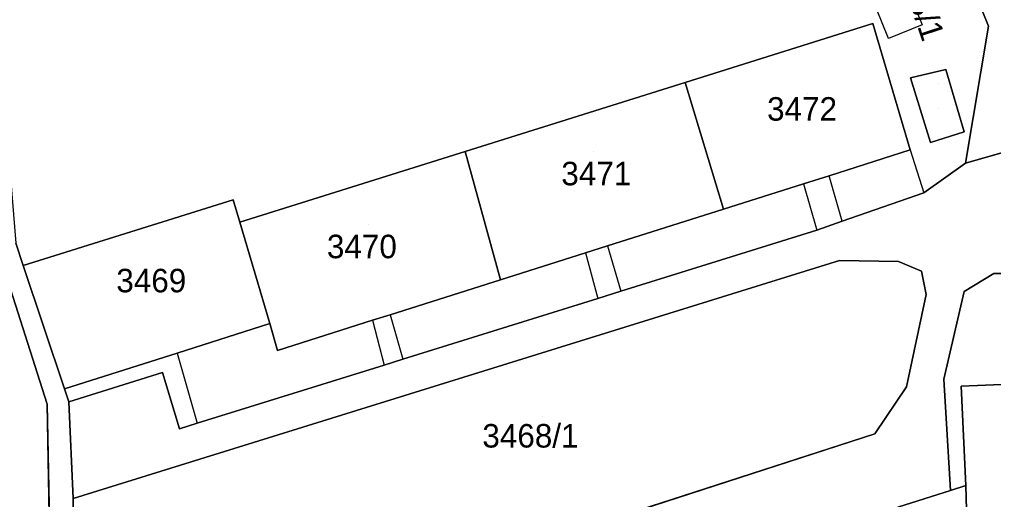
# Model space of a CAD drawing. Extents: x -264070 to -262271, y -1238894 to -1238141.
# Drawn here: x -262871.5 to -262788.6, y -1238496.4 to -1238455.5 of the extents above; entities that cross this region are included whole.
import ezdxf

# ---------------------------------------------------------------- set-up
doc = ezdxf.new("R2010")
doc.units = 0
for name, color, linetype in [('body_kn', 7, 'Continuous'), ('kladpar_druhypozemkov', 7, 'Continuous'), ('kladpar_hranice', 7, 'Continuous'), ('kladpar_parcelnecisla', 7, 'Continuous'), ('kladpar_plochy', 7, 'Continuous'), ('kladpar_sipky', 7, 'Continuous'), ('tarchy_linie', 7, 'Continuous'), ('zappar_hrandruhpozemk', 7, 'Continuous')]:
    doc.layers.add(name, color=color, linetype=linetype)

msp = doc.modelspace()

# ---------------------------------------------------------------- linework, layer by layer
at = {"layer": 'body_kn'}
for p, q in [((-262798.88, -1238455.89), (-262798.88, -1238455.89)), ((-262798.88, -1238455.89), (-262798.88, -1238455.89)), ((-262794.68, -1238456.01), (-262794.68, -1238456.01)), ((-262789.05, -1238456.12), (-262789.05, -1238456.12)), ((-262797.54, -1238457.17), (-262797.54, -1238457.17)), ((-262792.67, -1238459.81), (-262792.67, -1238459.81)), ((-262792.67, -1238459.81), (-262792.67, -1238459.81)), ((-262814.84, -1238460.9), (-262814.84, -1238460.9)), ((-262814.84, -1238460.9), (-262814.84, -1238460.9)), ((-262795.68, -1238460.51), (-262795.68, -1238460.51)), ((-262791.11, -1238465.11), (-262791.11, -1238465.11)), ((-262793.97, -1238466), (-262793.97, -1238466)), ((-262833.57, -1238466.77), (-262833.57, -1238466.77)), ((-262833.57, -1238466.77), (-262833.57, -1238466.77)), ((-262795.7, -1238466.64), (-262795.7, -1238466.64)), ((-262795.7, -1238466.64), (-262795.7, -1238466.64)), ((-262791, -1238467.76), (-262791, -1238467.76)), ((-262802.6, -1238468.83), (-262802.6, -1238468.83)), ((-262804.79, -1238469.52), (-262804.79, -1238469.52)), ((-262804.79, -1238469.52), (-262804.79, -1238469.52)), ((-262794.56, -1238470.28), (-262794.56, -1238470.28)), ((-262853.31, -1238470.87), (-262853.31, -1238470.87)), ((-262853.31, -1238470.87), (-262853.31, -1238470.87)), ((-262811.58, -1238471.67), (-262811.58, -1238471.67)), ((-262852.74, -1238472.78), (-262852.74, -1238472.78)), ((-262801.49, -1238472.7), (-262801.49, -1238472.7)), ((-262801.49, -1238472.7), (-262801.49, -1238472.7)), ((-262803.65, -1238473.46), (-262803.65, -1238473.46)), ((-262821.46, -1238474.8), (-262821.46, -1238474.8)), ((-262821.46, -1238474.8), (-262821.46, -1238474.8)), ((-262823.33, -1238475.39), (-262823.33, -1238475.39)), ((-262823.33, -1238475.39), (-262823.33, -1238475.39)), ((-262801.73, -1238476.05), (-262801.73, -1238476.05)), ((-262801.73, -1238476.05), (-262801.73, -1238476.05)), ((-262871.16, -1238476.48), (-262871.16, -1238476.48)), ((-262796.69, -1238476.13), (-262796.69, -1238476.13)), ((-262830.55, -1238477.68), (-262830.55, -1238477.68)), ((-262794.75, -1238476.95), (-262794.75, -1238476.95)), ((-262822.28, -1238479.26), (-262822.28, -1238479.26)), ((-262820.33, -1238478.65), (-262820.33, -1238478.65)), ((-262794.34, -1238478.93), (-262794.34, -1238478.93)), ((-262791.12, -1238478.68), (-262791.12, -1238478.68)), ((-262839.96, -1238480.66), (-262839.96, -1238480.66)), ((-262839.96, -1238480.66), (-262839.96, -1238480.66)), ((-262850.19, -1238481.41), (-262850.19, -1238481.41)), ((-262841.46, -1238481.13), (-262841.46, -1238481.13)), ((-262841.46, -1238481.13), (-262841.46, -1238481.13)), ((-262858.08, -1238483.92), (-262858.08, -1238483.92)), ((-262858.08, -1238483.92), (-262858.08, -1238483.92)), ((-262849.54, -1238483.69), (-262849.54, -1238483.69)), ((-262840.47, -1238484.93), (-262840.47, -1238484.93)), ((-262838.88, -1238484.43), (-262838.88, -1238484.43)), ((-262859.32, -1238485.56), (-262859.32, -1238485.56)), ((-262796.01, -1238486.8), (-262796.01, -1238486.8)), ((-262792.85, -1238486.14), (-262792.85, -1238486.14)), ((-262791.38, -1238486.73), (-262791.38, -1238486.73)), ((-262867.65, -1238486.97), (-262867.65, -1238486.97)), ((-262869.12, -1238488.27), (-262869.12, -1238488.27)), ((-262867.28, -1238488.07), (-262867.28, -1238488.07)), ((-262856.37, -1238489.88), (-262856.37, -1238489.88)), ((-262857.86, -1238490.35), (-262857.86, -1238490.35)), ((-262798.71, -1238490.79), (-262798.71, -1238490.79)), ((-262792.28, -1238495.59), (-262792.28, -1238495.59)), ((-262792.28, -1238495.59), (-262792.28, -1238495.59)), ((-262790.97, -1238495.17), (-262790.97, -1238495.17)), ((-262866.91, -1238496.29), (-262866.91, -1238496.29))]:
    msp.add_line(p, q, dxfattribs=at)
at = {"layer": 'kladpar_druhypozemkov'}
for p, q in [((-262804.43, -1238461.85), (-262804.43, -1238461.85)), ((-262793.31, -1238463.11), (-262793.31, -1238463.11)), ((-262822.63, -1238466.75), (-262822.63, -1238466.75)), ((-262841.83, -1238472.95), (-262841.83, -1238472.95)), ((-262859.63, -1238476.45), (-262859.63, -1238476.45)), ((-262827.03, -1238489.35), (-262827.03, -1238489.35))]:
    msp.add_line(p, q, dxfattribs=at)
at = {"layer": 'kladpar_hranice'}
for points in [[(-262813.03, -1238423.69), (-262816.48, -1238412.84), (-262832.44, -1238417.74), (-262850.86, -1238423.39), (-262870.49, -1238429.42), (-262871.1, -1238427.48), (-262888.61, -1238433.21), (-262885.22, -1238444.06), (-262877.38, -1238441.43), (-262874.97, -1238450.05), (-262873.29, -1238475.29), (-262869.12, -1238488.27), (-262868.55, -1238519.74), (-262897.95, -1238490.56), (-262896.25, -1238489.53), (-262912.76, -1238461.97), (-262925.07, -1238441.97), (-262929.57, -1238426.37), (-262924.66, -1238395.24), (-262923.4, -1238385.27), (-262921.26, -1238376.48), (-262918.98, -1238368.62), (-262909.71, -1238368.87)], [(-262786.55, -1238466.5), (-262791, -1238467.76), (-262789.05, -1238456.12), (-262800.89, -1238426.81), (-262801.71, -1238424.83), (-262809.3, -1238407.15)], [(-262839.65, -1238435.96), (-262838.66, -1238435.66), (-262837.63, -1238435.36), (-262821.25, -1238430.56), (-262819.19, -1238429.96), (-262811.78, -1238427.78), (-262801.71, -1238424.83), (-262800.89, -1238426.81), (-262841.06, -1238439.47), (-262873.85, -1238449.49), (-262871.8, -1238474.58), (-262871.16, -1238476.48), (-262867.65, -1238486.97), (-262867.28, -1238488.07), (-262866.91, -1238496.29), (-262866.54, -1238519.8)], [(-262800.89, -1238426.81), (-262789.05, -1238456.12), (-262791, -1238467.76), (-262794.56, -1238470.28), (-262801.49, -1238472.7), (-262803.65, -1238473.46), (-262820.33, -1238478.65), (-262822.28, -1238479.26), (-262838.88, -1238484.43), (-262840.47, -1238484.93), (-262856.37, -1238489.88), (-262857.86, -1238490.35), (-262859.32, -1238485.56), (-262867.28, -1238488.07), (-262867.65, -1238486.97), (-262858.08, -1238483.92), (-262850.19, -1238481.41), (-262849.54, -1238483.69), (-262841.46, -1238481.13), (-262839.96, -1238480.66), (-262830.55, -1238477.68), (-262823.33, -1238475.39), (-262821.46, -1238474.8), (-262811.58, -1238471.67), (-262804.79, -1238469.52), (-262802.6, -1238468.83), (-262795.7, -1238466.64), (-262798.88, -1238455.89), (-262814.84, -1238460.9), (-262833.57, -1238466.77), (-262852.74, -1238472.78), (-262853.31, -1238470.87), (-262871.16, -1238476.48), (-262871.8, -1238474.58)], [(-262868.55, -1238519.74), (-262869.12, -1238488.27), (-262873.29, -1238475.29), (-262874.97, -1238450.05), (-262877.38, -1238441.43), (-262875.45, -1238440.82), (-262873.87, -1238446.1), (-262858.47, -1238441.53), (-262856.5, -1238440.95), (-262839.65, -1238435.96)], [(-262798.88, -1238455.89), (-262795.7, -1238466.64), (-262802.6, -1238468.83), (-262804.79, -1238469.52), (-262811.58, -1238471.67), (-262814.84, -1238460.9), (-262798.88, -1238455.89)], [(-262795.68, -1238460.51), (-262793.97, -1238466), (-262791.11, -1238465.11), (-262792.67, -1238459.81), (-262795.68, -1238460.51)], [(-262792.67, -1238459.81), (-262791.11, -1238465.11), (-262793.97, -1238466), (-262795.68, -1238460.51), (-262792.67, -1238459.81)], [(-262814.84, -1238460.9), (-262811.58, -1238471.67), (-262821.46, -1238474.8), (-262823.33, -1238475.39), (-262830.55, -1238477.68), (-262833.57, -1238466.77), (-262814.84, -1238460.9)], [(-262822.66, -1238498.53), (-262798.71, -1238490.79), (-262796.01, -1238486.8), (-262794.34, -1238478.93), (-262794.75, -1238476.95), (-262796.69, -1238476.13), (-262801.73, -1238476.05), (-262866.91, -1238496.29), (-262867.28, -1238488.07), (-262859.32, -1238485.56), (-262857.86, -1238490.35), (-262856.37, -1238489.88), (-262840.47, -1238484.93), (-262838.88, -1238484.43), (-262822.28, -1238479.26), (-262820.33, -1238478.65), (-262803.65, -1238473.46), (-262801.49, -1238472.7), (-262794.56, -1238470.28), (-262791, -1238467.76), (-262786.55, -1238466.5)], [(-262833.57, -1238466.77), (-262830.55, -1238477.68), (-262839.96, -1238480.66), (-262841.46, -1238481.13), (-262849.54, -1238483.69), (-262850.19, -1238481.41), (-262852.74, -1238472.78), (-262833.57, -1238466.77)], [(-262853.31, -1238470.87), (-262852.74, -1238472.78), (-262850.19, -1238481.41), (-262858.08, -1238483.92), (-262867.65, -1238486.97), (-262871.16, -1238476.48), (-262853.31, -1238470.87)], [(-262801.73, -1238476.05), (-262796.69, -1238476.13), (-262794.75, -1238476.95), (-262794.34, -1238478.93), (-262796.01, -1238486.8), (-262798.71, -1238490.79), (-262822.66, -1238498.53), (-262843.84, -1238505.92), (-262843.78, -1238510.52), (-262866.54, -1238519.8), (-262866.91, -1238496.29), (-262801.73, -1238476.05)], [(-262716.29, -1238486.45), (-262724.95, -1238486.89), (-262724.99, -1238486.89), (-262727.29, -1238484.6), (-262735.52, -1238478.94), (-262739.33, -1238477.61), (-262755.49, -1238477.75), (-262761.74, -1238477.14), (-262788.6, -1238477.15), (-262791.12, -1238478.68), (-262792.85, -1238486.14), (-262792.28, -1238495.59), (-262796.77, -1238497.02)], [(-262739.33, -1238477.61), (-262735.52, -1238478.94), (-262727.29, -1238484.6), (-262724.99, -1238486.89), (-262737.05, -1238487.48), (-262737.11, -1238486.08), (-262739.45, -1238486.09), (-262739.57, -1238484.61), (-262791.38, -1238486.73), (-262790.97, -1238495.17), (-262792.28, -1238495.59), (-262792.85, -1238486.14), (-262791.12, -1238478.68), (-262788.6, -1238477.15), (-262761.74, -1238477.14), (-262755.49, -1238477.75), (-262739.33, -1238477.61)], [(-262739.57, -1238484.61), (-262739.45, -1238486.09), (-262738.4, -1238505.46), (-262738.27, -1238508.71), (-262790.72, -1238510.89), (-262790.77, -1238502.37), (-262790.97, -1238495.17), (-262791.38, -1238486.73), (-262739.57, -1238484.61)], [(-262792.28, -1238495.59), (-262790.97, -1238495.17), (-262790.77, -1238502.37), (-262794.66, -1238503.61), (-262796.77, -1238497.02), (-262792.28, -1238495.59)]]:
    msp.add_lwpolyline(points, dxfattribs=at)
at = {"layer": 'kladpar_plochy'}
for p, q in [((-262800.89, -1238426.81), (-262789.05, -1238456.12)), ((-262798.88, -1238455.89), (-262814.84, -1238460.9)), ((-262795.7, -1238466.64), (-262798.88, -1238455.89)), ((-262789.05, -1238456.12), (-262791, -1238467.76)), ((-262792.67, -1238459.81), (-262795.68, -1238460.51)), ((-262791.11, -1238465.11), (-262792.67, -1238459.81)), ((-262814.84, -1238460.9), (-262833.57, -1238466.77)), ((-262795.68, -1238460.51), (-262793.97, -1238466)), ((-262793.97, -1238466), (-262791.11, -1238465.11)), ((-262833.57, -1238466.77), (-262852.74, -1238472.78)), ((-262802.6, -1238468.83), (-262795.7, -1238466.64)), ((-262791, -1238467.76), (-262786.55, -1238466.5)), ((-262791, -1238467.76), (-262794.56, -1238470.28)), ((-262794.56, -1238470.28), (-262791, -1238467.76)), ((-262804.79, -1238469.52), (-262802.6, -1238468.83)), ((-262811.58, -1238471.67), (-262804.79, -1238469.52)), ((-262794.56, -1238470.28), (-262801.49, -1238472.7)), ((-262801.49, -1238472.7), (-262794.56, -1238470.28)), ((-262853.31, -1238470.87), (-262871.16, -1238476.48)), ((-262852.74, -1238472.78), (-262853.31, -1238470.87)), ((-262821.46, -1238474.8), (-262811.58, -1238471.67)), ((-262801.49, -1238472.7), (-262803.65, -1238473.46)), ((-262803.65, -1238473.46), (-262801.49, -1238472.7)), ((-262803.65, -1238473.46), (-262820.33, -1238478.65)), ((-262820.33, -1238478.65), (-262803.65, -1238473.46)), ((-262871.16, -1238476.48), (-262871.8, -1238474.58)), ((-262823.33, -1238475.39), (-262821.46, -1238474.8)), ((-262873.29, -1238475.29), (-262869.12, -1238488.27)), ((-262801.73, -1238476.05), (-262866.91, -1238496.29)), ((-262830.55, -1238477.68), (-262823.33, -1238475.39)), ((-262796.69, -1238476.13), (-262801.73, -1238476.05)), ((-262794.75, -1238476.95), (-262796.69, -1238476.13)), ((-262839.96, -1238480.66), (-262830.55, -1238477.68)), ((-262794.34, -1238478.93), (-262794.75, -1238476.95)), ((-262788.6, -1238477.15), (-262791.12, -1238478.68)), ((-262822.28, -1238479.26), (-262838.88, -1238484.43)), ((-262838.88, -1238484.43), (-262822.28, -1238479.26)), ((-262820.33, -1238478.65), (-262822.28, -1238479.26)), ((-262822.28, -1238479.26), (-262820.33, -1238478.65)), ((-262796.01, -1238486.8), (-262794.34, -1238478.93)), ((-262791.12, -1238478.68), (-262792.85, -1238486.14)), ((-262841.46, -1238481.13), (-262839.96, -1238480.66)), ((-262858.08, -1238483.92), (-262850.19, -1238481.41)), ((-262850.19, -1238481.41), (-262849.54, -1238483.69)), ((-262849.54, -1238483.69), (-262841.46, -1238481.13)), ((-262867.65, -1238486.97), (-262858.08, -1238483.92)), ((-262840.47, -1238484.93), (-262856.37, -1238489.88)), ((-262856.37, -1238489.88), (-262840.47, -1238484.93)), ((-262838.88, -1238484.43), (-262840.47, -1238484.93)), ((-262840.47, -1238484.93), (-262838.88, -1238484.43)), ((-262859.32, -1238485.56), (-262867.28, -1238488.07)), ((-262867.28, -1238488.07), (-262859.32, -1238485.56)), ((-262857.86, -1238490.35), (-262859.32, -1238485.56)), ((-262859.32, -1238485.56), (-262857.86, -1238490.35)), ((-262798.71, -1238490.79), (-262796.01, -1238486.8)), ((-262792.85, -1238486.14), (-262792.28, -1238495.59)), ((-262867.28, -1238488.07), (-262867.65, -1238486.97)), ((-262869.12, -1238488.27), (-262868.55, -1238519.74)), ((-262866.91, -1238496.29), (-262867.28, -1238488.07)), ((-262856.37, -1238489.88), (-262857.86, -1238490.35)), ((-262857.86, -1238490.35), (-262856.37, -1238489.88)), ((-262822.66, -1238498.53), (-262798.71, -1238490.79)), ((-262792.28, -1238495.59), (-262796.77, -1238497.02))]:
    msp.add_line(p, q, dxfattribs=at)
for points in [[(-262786.55, -1238466.5), (-262791, -1238467.76), (-262789.05, -1238456.12), (-262800.89, -1238426.81), (-262801.71, -1238424.83), (-262809.3, -1238407.15)], [(-262871.8, -1238474.58), (-262871.16, -1238476.48), (-262867.65, -1238486.97), (-262867.28, -1238488.07), (-262866.91, -1238496.29), (-262866.54, -1238519.8)], [(-262868.55, -1238519.74), (-262869.12, -1238488.27), (-262873.29, -1238475.29)]]:
    msp.add_lwpolyline(points, dxfattribs=at)
for points in [[(-262798.88, -1238455.89), (-262795.7, -1238466.64), (-262802.6, -1238468.83), (-262804.79, -1238469.52), (-262811.58, -1238471.67), (-262814.84, -1238460.9)], [(-262792.67, -1238459.81), (-262791.11, -1238465.11), (-262793.97, -1238466), (-262795.68, -1238460.51)], [(-262814.84, -1238460.9), (-262811.58, -1238471.67), (-262821.46, -1238474.8), (-262823.33, -1238475.39), (-262830.55, -1238477.68), (-262833.57, -1238466.77)], [(-262833.57, -1238466.77), (-262830.55, -1238477.68), (-262839.96, -1238480.66), (-262841.46, -1238481.13), (-262849.54, -1238483.69), (-262850.19, -1238481.41), (-262852.74, -1238472.78)], [(-262853.31, -1238470.87), (-262852.74, -1238472.78), (-262850.19, -1238481.41), (-262858.08, -1238483.92), (-262867.65, -1238486.97), (-262871.16, -1238476.48)], [(-262801.73, -1238476.05), (-262796.69, -1238476.13), (-262794.75, -1238476.95), (-262794.34, -1238478.93), (-262796.01, -1238486.8), (-262798.71, -1238490.79), (-262822.66, -1238498.53), (-262843.84, -1238505.92), (-262843.78, -1238510.52), (-262866.54, -1238519.8), (-262866.91, -1238496.29)], [(-262739.33, -1238477.61), (-262735.52, -1238478.94), (-262727.29, -1238484.6), (-262724.99, -1238486.89), (-262737.05, -1238487.48), (-262737.11, -1238486.08), (-262739.45, -1238486.09), (-262739.57, -1238484.61), (-262791.38, -1238486.73), (-262790.97, -1238495.17), (-262792.28, -1238495.59), (-262792.85, -1238486.14), (-262791.12, -1238478.68), (-262788.6, -1238477.15), (-262761.74, -1238477.14), (-262755.49, -1238477.75)], [(-262739.57, -1238484.61), (-262739.45, -1238486.09), (-262738.4, -1238505.46), (-262738.27, -1238508.71), (-262790.72, -1238510.89), (-262790.77, -1238502.37), (-262790.97, -1238495.17), (-262791.38, -1238486.73)], [(-262792.28, -1238495.59), (-262790.97, -1238495.17), (-262790.77, -1238502.37), (-262794.66, -1238503.61), (-262796.77, -1238497.02)]]:
    msp.add_lwpolyline(points, close=True, dxfattribs=at)
at = {"layer": 'kladpar_sipky'}
msp.add_line((-262793.31, -1238461.01), (-262793.31, -1238461.01), dxfattribs=at)
at = {"layer": 'tarchy_linie'}
msp.add_lwpolyline([(-262817.63, -1238398.03), (-262815.88, -1238403.64), (-262794.68, -1238456.01), (-262797.54, -1238457.17), (-262818.82, -1238404.57), (-262818.44, -1238404.46), (-262818.88, -1238403.01), (-262820.13, -1238398.69), (-262819.12, -1238398.42), (-262817.63, -1238398.03)], dxfattribs=at)
at = {"layer": 'zappar_hrandruhpozemk'}
for p, q in [((-262795.7, -1238466.64), (-262794.56, -1238470.28)), ((-262801.49, -1238472.7), (-262802.6, -1238468.83)), ((-262804.79, -1238469.52), (-262803.65, -1238473.46)), ((-262821.46, -1238474.8), (-262820.33, -1238478.65)), ((-262823.33, -1238475.39), (-262822.28, -1238479.26)), ((-262839.96, -1238480.66), (-262838.88, -1238484.43)), ((-262841.46, -1238481.13), (-262840.47, -1238484.93)), ((-262858.08, -1238483.92), (-262856.37, -1238489.88))]:
    msp.add_line(p, q, dxfattribs=at)

# ---------------------------------------------------------------- texts
at = {"layer": 'kladpar_parcelnecisla'}
msp.add_text('3473/1', height=2, rotation=288, dxfattribs=at).set_placement((-262797.182, -1238449.746))
for s, p in [('3472', (-262807.882, -1238464.15)), ('3471', (-262825.386, -1238469.65)), ('3470', (-262845.327, -1238475.85)), ('3469', (-262863.242, -1238478.75)), ('3468/1', (-262832.104, -1238491.95))]:
    msp.add_text(s, height=2, dxfattribs=at).set_placement(p)

doc.saveas('drawing.dxf')
